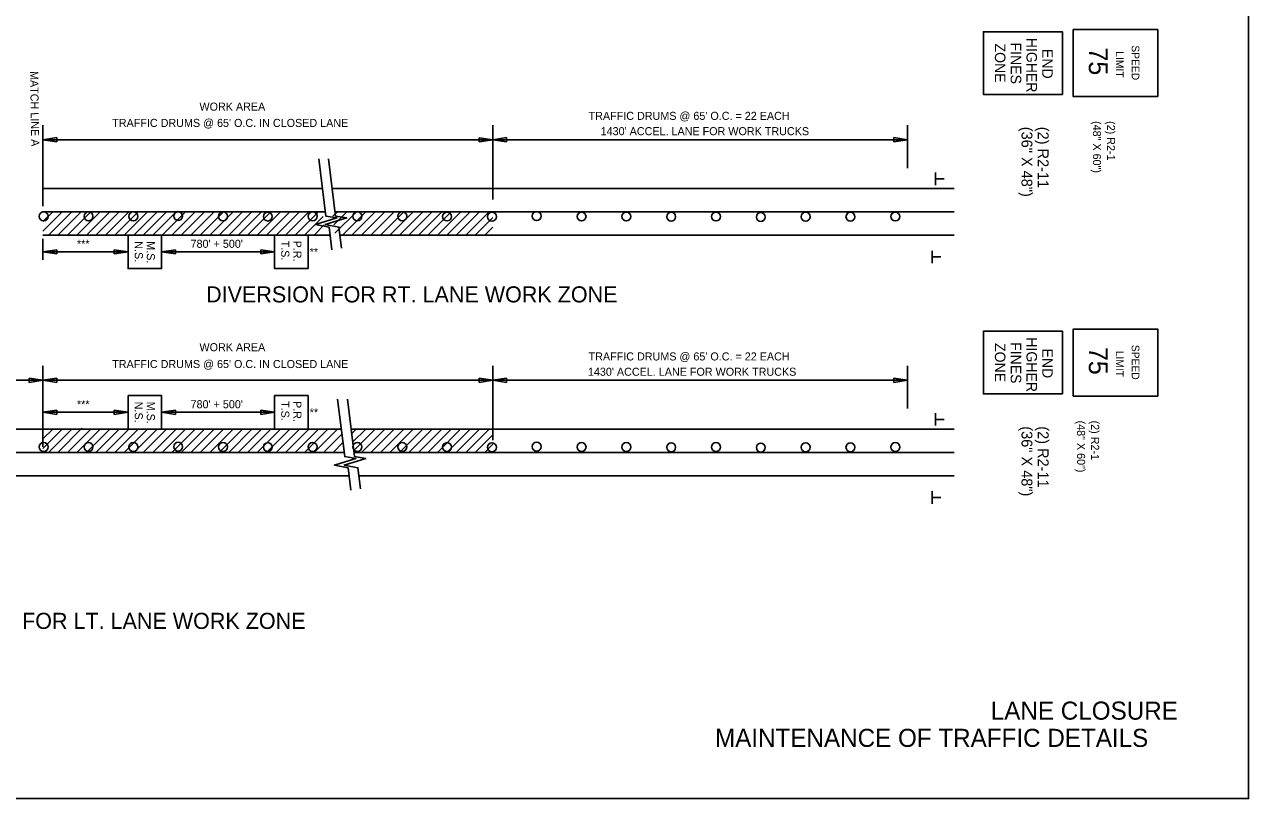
# Model space of a CAD drawing. Extents: x 1374027 to 1374537, y 380415 to 381405.
# Drawn here: x 1374105.8 to 1374197.1, y 380855.2 to 380912.9 of the extents above; entities that cross this region are included whole.
import ezdxf

# ---------------------------------------------------------------- set-up
doc = ezdxf.new("R2010")
doc.units = 0
for name, color, linetype in [('Default', 7, 'Continuous'), ('DSN_DRFT_Junk-No-Plot', 7, 'Continuous'), ('R_Border Notes', 7, 'Continuous'), ('R_MOT', 7, 'Continuous')]:
    doc.layers.add(name, color=color, linetype=linetype)

msp = doc.modelspace()

# ---------------------------------------------------------------- linework, layer by layer
at = {"layer": 'Default'}
for p, q in [((1374107.216, 380905.388), (1374107.216, 380899.353)), ((1374140.751, 380905.388), (1374140.751, 380899.853)), ((1374171.661, 380905.388), (1374171.661, 380902.196)), ((1374107.216, 380904.309), (1374108.246, 380904.464)), ((1374107.216, 380904.457), (1374107.216, 380899.353)), ((1374107.216, 380904.456), (1374107.216, 380899.353)), ((1374107.216, 380904.456), (1374107.216, 380899.353)), ((1374140.751, 380904.309), (1374107.216, 380904.309)), ((1374108.246, 380904.155), (1374107.216, 380904.309)), ((1374108.246, 380904.464), (1374108.246, 380904.155)), ((1374139.72, 380904.155), (1374139.72, 380904.463)), ((1374139.72, 380904.463), (1374140.751, 380904.309)), ((1374140.751, 380904.309), (1374139.72, 380904.155)), ((1374140.751, 380904.309), (1374141.781, 380904.464)), ((1374171.661, 380904.309), (1374140.751, 380904.309)), ((1374141.781, 380904.155), (1374140.751, 380904.309)), ((1374141.781, 380904.464), (1374141.781, 380904.155)), ((1374170.631, 380904.155), (1374170.631, 380904.464)), ((1374170.631, 380904.464), (1374171.661, 380904.309)), ((1374171.661, 380904.309), (1374170.631, 380904.155)), ((1374173.748, 380900.932), (1374173.748, 380901.86)), ((1374173.762, 380901.394), (1374174.395, 380901.394)), ((1374107.216, 380900.672), (1374128.047, 380900.672)), ((1374128.776, 380900.672), (1374140.751, 380900.672)), ((1374140.751, 380900.672), (1374175.139, 380900.672)), ((1374107.146, 380898.933), (1374128.265, 380898.933)), ((1374107.216, 380897.494), (1374108.655, 380898.933)), ((1374107.216, 380898.201), (1374107.948, 380898.933)), ((1374107.624, 380897.195), (1374109.363, 380898.933)), ((1374108.331, 380897.195), (1374110.125, 380898.989)), ((1374109.038, 380897.195), (1374110.777, 380898.933)), ((1374109.746, 380897.195), (1374111.484, 380898.933)), ((1374110.453, 380897.195), (1374112.191, 380898.933)), ((1374111.16, 380897.195), (1374112.898, 380898.933)), ((1374111.867, 380897.195), (1374113.605, 380898.933)), ((1374112.574, 380897.195), (1374114.312, 380898.933)), ((1374113.281, 380897.195), (1374115.019, 380898.933)), ((1374113.988, 380897.195), (1374115.727, 380898.933)), ((1374114.695, 380897.195), (1374116.434, 380898.933)), ((1374115.402, 380897.195), (1374117.141, 380898.933)), ((1374116.11, 380897.195), (1374117.848, 380898.933)), ((1374116.817, 380897.195), (1374118.555, 380898.933)), ((1374117.524, 380897.195), (1374119.262, 380898.933)), ((1374118.231, 380897.195), (1374119.969, 380898.933)), ((1374118.938, 380897.195), (1374120.676, 380898.933)), ((1374119.645, 380897.195), (1374121.383, 380898.933)), ((1374120.352, 380897.195), (1374122.09, 380898.933)), ((1374121.059, 380897.195), (1374122.798, 380898.933)), ((1374121.766, 380897.195), (1374123.505, 380898.933)), ((1374122.474, 380897.195), (1374124.212, 380898.933)), ((1374123.181, 380897.195), (1374124.919, 380898.933)), ((1374123.888, 380897.195), (1374125.626, 380898.933)), ((1374124.595, 380897.195), (1374126.333, 380898.933)), ((1374125.302, 380897.195), (1374127.04, 380898.933)), ((1374126.009, 380897.195), (1374127.747, 380898.933)), ((1374126.716, 380897.195), (1374128.105, 380898.584)), ((1374128.831, 380898.603), (1374129.162, 380898.933)), ((1374128.907, 380897.972), (1374129.869, 380898.933)), ((1374128.983, 380897.34), (1374130.576, 380898.933)), ((1374128.993, 380898.933), (1374140.751, 380898.933)), ((1374129.545, 380897.195), (1374131.283, 380898.933)), ((1374130.252, 380897.195), (1374131.99, 380898.933)), ((1374130.959, 380897.195), (1374132.697, 380898.933)), ((1374131.666, 380897.195), (1374133.404, 380898.933)), ((1374132.373, 380897.195), (1374134.111, 380898.933)), ((1374133.08, 380897.195), (1374134.818, 380898.933)), ((1374133.787, 380897.195), (1374135.525, 380898.933)), ((1374134.494, 380897.195), (1374136.233, 380898.933)), ((1374135.201, 380897.195), (1374136.94, 380898.933)), ((1374135.909, 380897.195), (1374137.647, 380898.933)), ((1374136.616, 380897.195), (1374138.354, 380898.933)), ((1374137.323, 380897.195), (1374139.061, 380898.933)), ((1374138.03, 380897.195), (1374139.768, 380898.933)), ((1374138.737, 380897.195), (1374140.475, 380898.933)), ((1374139.444, 380897.195), (1374140.751, 380898.502)), ((1374140.751, 380898.933), (1374175.139, 380898.933)), ((1374127.423, 380897.195), (1374128.181, 380897.953)), ((1374140.151, 380897.195), (1374140.751, 380897.795)), ((1374107.194, 380897.195), (1374128.619, 380897.195)), ((1374107.216, 380896.929), (1374107.216, 380895.353)), ((1374129.347, 380897.195), (1374140.751, 380897.195)), ((1374140.751, 380897.195), (1374175.139, 380897.195)), ((1374107.216, 380895.945), (1374108.246, 380896.1)), ((1374113.558, 380895.945), (1374107.216, 380895.945)), ((1374108.246, 380895.79), (1374107.216, 380895.945)), ((1374108.246, 380896.1), (1374108.246, 380895.79)), ((1374112.528, 380895.79), (1374112.528, 380896.1)), ((1374112.528, 380896.1), (1374113.558, 380895.945)), ((1374113.558, 380895.945), (1374112.528, 380895.79)), ((1374116.058, 380895.945), (1374117.088, 380896.1)), ((1374124.479, 380895.945), (1374116.058, 380895.945)), ((1374117.088, 380895.79), (1374116.058, 380895.945)), ((1374117.088, 380896.1), (1374117.088, 380895.79)), ((1374123.448, 380895.79), (1374123.448, 380896.1)), ((1374123.448, 380896.1), (1374124.479, 380895.945)), ((1374124.479, 380895.945), (1374123.448, 380895.79)), ((1374173.508, 380895.105), (1374173.508, 380896.033)), ((1374173.522, 380895.567), (1374174.155, 380895.567)), ((1374107.216, 380887.446), (1374107.216, 380881.411)), ((1374140.751, 380887.446), (1374140.751, 380881.911)), ((1374171.661, 380887.446), (1374171.661, 380884.254)), ((1374107.216, 380886.368), (1374076.305, 380886.368)), ((1374106.185, 380886.213), (1374106.185, 380886.522)), ((1374106.185, 380886.522), (1374107.216, 380886.368)), ((1374107.216, 380886.368), (1374106.185, 380886.213)), ((1374107.216, 380886.368), (1374108.246, 380886.522)), ((1374107.216, 380886.515), (1374107.216, 380881.411)), ((1374107.216, 380886.514), (1374107.216, 380881.411)), ((1374107.216, 380886.514), (1374107.216, 380881.411)), ((1374140.751, 380886.368), (1374107.216, 380886.368)), ((1374108.246, 380886.213), (1374107.216, 380886.368)), ((1374108.246, 380886.522), (1374108.246, 380886.213)), ((1374139.72, 380886.213), (1374139.72, 380886.522)), ((1374139.72, 380886.522), (1374140.751, 380886.368)), ((1374140.751, 380886.368), (1374139.72, 380886.213)), ((1374140.751, 380886.368), (1374141.781, 380886.522)), ((1374171.661, 380886.368), (1374140.751, 380886.368)), ((1374141.781, 380886.213), (1374140.751, 380886.368)), ((1374141.781, 380886.522), (1374141.781, 380886.213)), ((1374170.631, 380886.213), (1374170.631, 380886.522)), ((1374170.631, 380886.522), (1374171.661, 380886.368)), ((1374171.661, 380886.368), (1374170.631, 380886.213)), ((1374107.216, 380884.964), (1374107.216, 380883.388)), ((1374107.216, 380883.98), (1374108.246, 380884.135)), ((1374113.558, 380883.98), (1374107.216, 380883.98)), ((1374108.246, 380883.825), (1374107.216, 380883.98)), ((1374108.246, 380884.135), (1374108.246, 380883.825)), ((1374112.528, 380883.825), (1374112.528, 380884.135)), ((1374112.528, 380884.135), (1374113.558, 380883.98)), ((1374113.558, 380883.98), (1374112.528, 380883.825)), ((1374116.058, 380883.98), (1374117.088, 380884.135)), ((1374124.479, 380883.98), (1374116.058, 380883.98)), ((1374117.088, 380883.825), (1374116.058, 380883.98)), ((1374117.088, 380884.135), (1374117.088, 380883.825)), ((1374123.448, 380883.825), (1374123.448, 380884.135)), ((1374123.448, 380884.135), (1374124.479, 380883.98)), ((1374124.479, 380883.98), (1374123.448, 380883.825)), ((1374173.748, 380882.991), (1374173.748, 380883.918)), ((1374173.762, 380883.452), (1374174.395, 380883.452)), ((1374103.946, 380882.73), (1374107.216, 380882.73)), ((1374107.216, 380882.73), (1374129.462, 380882.73)), ((1374107.216, 380881.291), (1374108.655, 380882.73)), ((1374107.216, 380881.998), (1374107.948, 380882.73)), ((1374107.624, 380880.992), (1374109.362, 380882.73)), ((1374108.331, 380880.992), (1374110.125, 380882.785)), ((1374109.038, 380880.992), (1374110.776, 380882.73)), ((1374109.745, 380880.992), (1374111.483, 380882.73)), ((1374110.452, 380880.992), (1374112.19, 380882.73)), ((1374111.159, 380880.992), (1374112.898, 380882.73)), ((1374111.866, 380880.992), (1374113.605, 380882.73)), ((1374112.574, 380880.992), (1374114.312, 380882.73)), ((1374113.281, 380880.992), (1374115.019, 380882.73)), ((1374113.988, 380880.992), (1374115.726, 380882.73)), ((1374114.695, 380880.992), (1374116.433, 380882.73)), ((1374115.402, 380880.992), (1374117.14, 380882.73)), ((1374116.109, 380880.992), (1374117.847, 380882.73)), ((1374116.816, 380880.992), (1374118.554, 380882.73)), ((1374117.523, 380880.992), (1374119.262, 380882.73)), ((1374118.23, 380880.992), (1374119.969, 380882.73)), ((1374118.937, 380880.992), (1374120.676, 380882.73)), ((1374119.645, 380880.992), (1374121.383, 380882.73)), ((1374120.352, 380880.992), (1374122.09, 380882.73)), ((1374121.059, 380880.992), (1374122.797, 380882.73)), ((1374121.766, 380880.992), (1374123.504, 380882.73)), ((1374122.473, 380880.992), (1374124.211, 380882.73)), ((1374123.18, 380880.992), (1374124.918, 380882.73)), ((1374123.887, 380880.992), (1374125.626, 380882.73)), ((1374124.594, 380880.992), (1374126.333, 380882.73)), ((1374125.301, 380880.992), (1374127.04, 380882.73)), ((1374126.009, 380880.992), (1374127.747, 380882.73)), ((1374126.716, 380880.992), (1374128.454, 380882.73)), ((1374127.423, 380880.992), (1374129.161, 380882.73)), ((1374128.13, 380880.992), (1374129.518, 380882.38)), ((1374130.19, 380882.73), (1374140.751, 380882.73)), ((1374130.245, 380882.399), (1374130.575, 380882.73)), ((1374130.32, 380881.768), (1374131.282, 380882.73)), ((1374130.396, 380881.137), (1374131.989, 380882.73)), ((1374130.958, 380880.992), (1374132.697, 380882.73)), ((1374131.665, 380880.992), (1374133.404, 380882.73)), ((1374132.373, 380880.992), (1374134.111, 380882.73)), ((1374133.08, 380880.992), (1374134.818, 380882.73)), ((1374133.787, 380880.992), (1374135.525, 380882.73)), ((1374134.494, 380880.992), (1374136.232, 380882.73)), ((1374135.201, 380880.992), (1374136.939, 380882.73)), ((1374135.908, 380880.992), (1374137.646, 380882.73)), ((1374136.615, 380880.992), (1374138.353, 380882.73)), ((1374137.322, 380880.992), (1374139.061, 380882.73)), ((1374138.029, 380880.992), (1374139.768, 380882.73)), ((1374138.736, 380880.992), (1374140.475, 380882.73)), ((1374139.444, 380880.992), (1374140.751, 380882.299)), ((1374140.751, 380882.73), (1374175.139, 380882.73)), ((1374128.837, 380880.992), (1374129.594, 380881.749)), ((1374140.151, 380880.992), (1374140.751, 380881.592)), ((1374104.164, 380880.992), (1374107.146, 380880.992)), ((1374107.146, 380880.992), (1374129.679, 380880.992)), ((1374130.407, 380880.992), (1374140.751, 380880.992)), ((1374140.751, 380880.992), (1374175.139, 380880.992)), ((1374104.518, 380879.253), (1374107.194, 380879.253)), ((1374107.194, 380879.253), (1374130.033, 380879.253)), ((1374130.761, 380879.253), (1374140.751, 380879.253)), ((1374140.751, 380879.253), (1374175.139, 380879.253)), ((1374173.508, 380877.164), (1374173.508, 380878.091)), ((1374173.522, 380877.625), (1374174.155, 380877.625))]:
    msp.add_line(p, q, dxfattribs=at)
for points in [[(1374190.32, 380907.528), (1374184.018, 380907.528), (1374184.018, 380912.529), (1374190.32, 380912.529)], [(1374113.558, 380897.195), (1374116.058, 380897.195), (1374116.058, 380894.695), (1374113.558, 380894.695)], [(1374124.479, 380897.195), (1374126.979, 380897.195), (1374126.979, 380894.695), (1374124.479, 380894.695)], [(1374190.32, 380885.19), (1374184.018, 380885.19), (1374184.018, 380890.191), (1374190.32, 380890.191)], [(1374113.558, 380885.23), (1374116.058, 380885.23), (1374116.058, 380882.73), (1374113.558, 380882.73)], [(1374124.479, 380885.23), (1374126.979, 380885.23), (1374126.979, 380882.73), (1374124.479, 380882.73)]]:
    msp.add_lwpolyline(points, close=True, dxfattribs=at)
for points in [[(1374127.77, 380902.894), (1374128.304, 380898.618), (1374129.13, 380898.472), (1374127.527, 380897.986), (1374128.547, 380897.792), (1374128.75, 380896.107)], [(1374128.498, 380902.894), (1374129.033, 380898.618), (1374129.858, 380898.472), (1374128.256, 380897.986), (1374129.275, 380897.792), (1374129.465, 380896.211)], [(1374129.184, 380884.952), (1374129.718, 380880.676), (1374130.544, 380880.53), (1374128.941, 380880.044), (1374129.961, 380879.85), (1374130.164, 380878.165)], [(1374129.913, 380884.952), (1374130.447, 380880.676), (1374131.272, 380880.53), (1374129.67, 380880.044), (1374130.69, 380879.85), (1374130.88, 380878.269)]]:
    msp.add_lwpolyline(points, dxfattribs=at)
for centre in [(1374107.271, 380898.591), (1374110.612, 380898.591), (1374113.953, 380898.592), (1374117.294, 380898.612), (1374120.635, 380898.591), (1374123.976, 380898.58), (1374127.317, 380898.596), (1374130.658, 380898.596), (1374133.999, 380898.596), (1374137.34, 380898.581), (1374140.682, 380898.568), (1374144.023, 380898.616), (1374147.364, 380898.584), (1374150.705, 380898.584), (1374154.046, 380898.568), (1374157.387, 380898.582), (1374160.728, 380898.546), (1374164.069, 380898.568), (1374167.41, 380898.565), (1374170.751, 380898.581), (1374107.271, 380881.394), (1374110.612, 380881.394), (1374113.953, 380881.395), (1374117.294, 380881.415), (1374120.635, 380881.394), (1374123.976, 380881.383), (1374127.317, 380881.399), (1374130.658, 380881.399), (1374133.999, 380881.399), (1374137.34, 380881.383), (1374140.682, 380881.371), (1374144.023, 380881.419), (1374147.364, 380881.387), (1374150.705, 380881.387), (1374154.046, 380881.371), (1374157.387, 380881.384), (1374160.728, 380881.349), (1374164.069, 380881.371), (1374167.41, 380881.368), (1374170.751, 380881.384)]:
    msp.add_circle(centre, 0.333, dxfattribs=at)
at = {"layer": 'DSN_DRFT_Junk-No-Plot'}
for points in [[(1374027.083, 380965.174), (1374197.083, 380965.174), (1374197.083, 380855.174), (1374027.083, 380855.174)], [(1374027.083, 380965.174), (1374027.083, 380855.174), (1374197.083, 380855.174), (1374197.083, 380965.174)]]:
    msp.add_lwpolyline(points, close=True, dxfattribs=at)
at = {"layer": 'R_MOT'}
for points in [[(1374183.211, 380907.691), (1374177.318, 380907.691), (1374177.318, 380912.366), (1374183.211, 380912.366)], [(1374183.211, 380885.352), (1374177.318, 380885.352), (1374177.318, 380890.028), (1374183.211, 380890.028)]]:
    msp.add_lwpolyline(points, close=True, dxfattribs=at)

# ---------------------------------------------------------------- texts
at = {"layer": 'Default'}
for s, height, rotation, p in [('SPEED', 0.5729, 270, (1374188.373, 380911.348)), ('75', 1.3959, 270, (1374185.18, 380911.196)), ('LIMIT', 0.5729, 270, (1374187.202, 380910.905)), ('MATCH LINE A', 0.6, 270.80593, (1374106.259, 380909.427)), ('(48" X 60")', 0.6, 270, (1374185.488, 380905.7)), ('(2) R2-1', 0.6, 270, (1374186.534, 380905.7)), ('N.S.', 0.6, 270, (1374114.058, 380896.736)), ('M.S.', 0.6, 270, (1374114.958, 380896.736)), ('T.S.', 0.6, 270, (1374124.979, 380896.784)), ('P.R.', 0.6, 270, (1374125.879, 380896.784)), ('75', 1.3959, 270, (1374185.18, 380888.858)), ('LIMIT', 0.5729, 270, (1374187.202, 380888.567)), ('SPEED', 0.5729, 270, (1374188.373, 380889.01)), ('N.S.', 0.6, 270, (1374114.058, 380884.771)), ('M.S.', 0.6, 270, (1374114.958, 380884.771)), ('T.S.', 0.6, 270, (1374124.979, 380884.819)), ('P.R.', 0.6, 270, (1374125.879, 380884.819)), ('(48" X 60")', 0.6, 270, (1374184.302, 380883.362)), ('(2) R2-1', 0.6, 270, (1374185.349, 380883.362))]:
    msp.add_text(s, height=height, rotation=rotation, dxfattribs=at).set_placement(p)
for s, height, p in [('WORK AREA', 0.6, (1374118.883, 380906.478)), ("TRAFFIC DRUMS @ 65' O.C. IN CLOSED LANE", 0.6, (1374112.379, 380905.263)), ("TRAFFIC DRUMS @ 65' O.C. = 22 EACH", 0.6, (1374147.888, 380905.789)), ("1430' ACCEL. LANE FOR WORK TRUCKS", 0.6, (1374148.788, 380904.647)), ('***', 0.6, (1374109.749, 380896.248)), ("780' + 500'", 0.6, (1374118.218, 380896.248)), ('**', 0.6, (1374127.102, 380895.645)), ('DIVERSION FOR RT. LANE WORK ZONE', 1.2, (1374119.375, 380892.175)), ('WORK AREA', 0.6, (1374118.883, 380888.536)), ("TRAFFIC DRUMS @ 65' O.C. = 22 EACH", 0.6, (1374147.888, 380887.847)), ("TRAFFIC DRUMS @ 65' O.C. IN CLOSED LANE", 0.6, (1374112.379, 380887.28)), ("1430' ACCEL. LANE FOR WORK TRUCKS", 0.6, (1374147.84, 380886.705)), ('***', 0.6, (1374109.749, 380884.283)), ("780' + 500'", 0.6, (1374118.218, 380884.283)), ('**', 0.6, (1374127.102, 380883.68)), ('DIVERSION FOR LT. LANE WORK ZONE', 1.2, (1374096.385, 380867.824))]:
    msp.add_text(s, height=height, dxfattribs=at).set_placement(p)
at = {"layer": 'R_Border Notes'}
for s, p in [('LANE CLOSURE', (1374177.871, 380861.056)), ('MAINTENANCE OF TRAFFIC DETAILS', (1374157.313, 380859.024))]:
    msp.add_text(s, height=1.35, dxfattribs=at).set_placement(p)
at = {"layer": 'R_MOT'}
for s, height, p in [('ZONE', 0.7843, (1374178.177, 380911.484)), ('FINES', 0.7843, (1374179.354, 380911.555)), ('HIGHER', 0.7844, (1374180.53, 380911.911)), ('END', 0.7844, (1374181.707, 380911.076)), ('(36" X 48")', 0.81, (1374180.161, 380905.275)), ('(2) R2-11', 0.81, (1374181.376, 380905.275)), ('HIGHER', 0.7844, (1374180.53, 380889.573)), ('ZONE', 0.7843, (1374178.177, 380889.146)), ('FINES', 0.7843, (1374179.354, 380889.217)), ('END', 0.7844, (1374181.707, 380888.738)), ('(36" X 48")', 0.81, (1374180.161, 380882.937)), ('(2) R2-11', 0.81, (1374181.376, 380882.937))]:
    msp.add_text(s, height=height, rotation=270, dxfattribs=at).set_placement(p)

doc.saveas('drawing.dxf')
